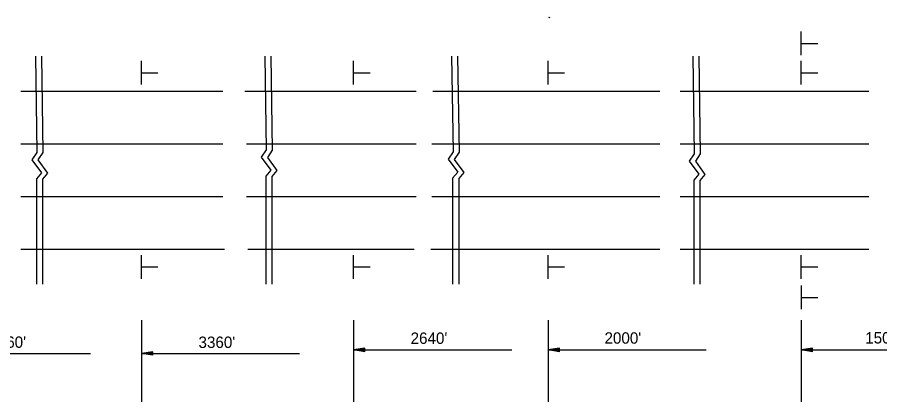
# Model space of a CAD drawing. Extents: x 1397271 to 1411271, y 376395 to 377888.
# Drawn here: x 1405137 to 1405825, y 377165 to 377471 of the extents above; entities that cross this region are included whole.
import ezdxf

# ---------------------------------------------------------------- set-up
doc = ezdxf.new("R2010")
doc.units = 0
doc.layers.add('Default', color=7, linetype='Continuous')
doc.layers.add('R_MOT', color=7, linetype='Continuous')

msp = doc.modelspace()

# ---------------------------------------------------------------- linework, layer by layer
at = {"layer": 'Default'}
for p, q in [((1405139.45, 377412.4), (1405300.59, 377412.4)), ((1405318.22, 377412.4), (1405454.76, 377412.4)), ((1405468.06, 377412.4), (1405649.17, 377412.4)), ((1405665.32, 377412.4), (1405815.76, 377412.4)), ((1405139.45, 377370.37), (1405300.59, 377370.37)), ((1405319.33, 377370.37), (1405454.76, 377370.37)), ((1405467.25, 377370.37), (1405649.17, 377370.37)), ((1405665.32, 377370.37), (1405815.76, 377370.37)), ((1405139.45, 377328.34), (1405300.59, 377328.34)), ((1405319.33, 377328.34), (1405454.76, 377328.34)), ((1405467.25, 377328.34), (1405649.17, 377328.34)), ((1405665.32, 377328.34), (1405815.76, 377328.34)), ((1405139.45, 377286.3), (1405301.98, 377286.3)), ((1405320.44, 377286.3), (1405453.12, 377286.3)), ((1405466.43, 377286.3), (1405649.17, 377286.3)), ((1405665.32, 377286.3), (1405815.76, 377286.3)), ((1405235.63, 377229.73), (1405235.63, 377164.82)), ((1405404.8, 377229.73), (1405404.8, 377164.82)), ((1405559.93, 377229.73), (1405559.93, 377164.82)), ((1405761.88, 377229.73), (1405761.88, 377164.82)), ((1405068.79, 377203.16), (1405194.97, 377203.16)), ((1405244.7, 377204.52), (1405235.63, 377203.16)), ((1405235.63, 377203.16), (1405361.81, 377203.16)), ((1405244.7, 377201.8), (1405235.63, 377203.16)), ((1405244.7, 377204.29), (1405237.15, 377203.16)), ((1405244.7, 377202.02), (1405237.15, 377203.16)), ((1405244.7, 377204.06), (1405238.7, 377203.16)), ((1405244.7, 377202.25), (1405238.7, 377203.16)), ((1405244.7, 377203.83), (1405240.21, 377203.16)), ((1405244.7, 377202.48), (1405240.21, 377203.16)), ((1405244.7, 377203.6), (1405241.75, 377203.16)), ((1405244.7, 377202.72), (1405241.75, 377203.16)), ((1405244.7, 377203.37), (1405243.27, 377203.16)), ((1405244.7, 377202.94), (1405243.27, 377203.16)), ((1405244.7, 377201.8), (1405244.7, 377204.52)), ((1405413.86, 377207.42), (1405404.8, 377206.06)), ((1405404.8, 377206.06), (1405530.98, 377206.06)), ((1405413.86, 377204.7), (1405404.8, 377206.06)), ((1405413.86, 377207.19), (1405406.31, 377206.06)), ((1405413.86, 377204.92), (1405406.31, 377206.06)), ((1405413.86, 377206.96), (1405407.87, 377206.06)), ((1405413.86, 377205.15), (1405407.87, 377206.06)), ((1405413.86, 377206.73), (1405409.38, 377206.06)), ((1405413.86, 377205.38), (1405409.38, 377206.06)), ((1405413.86, 377206.5), (1405410.92, 377206.06)), ((1405413.86, 377205.62), (1405410.92, 377206.06)), ((1405413.86, 377206.27), (1405412.43, 377206.06)), ((1405413.86, 377205.84), (1405412.43, 377206.06)), ((1405413.86, 377204.7), (1405413.86, 377207.42)), ((1405568.99, 377207.42), (1405559.93, 377206.06)), ((1405559.93, 377206.06), (1405686.11, 377206.06)), ((1405568.99, 377204.7), (1405559.93, 377206.06)), ((1405568.99, 377207.19), (1405561.44, 377206.06)), ((1405568.99, 377204.92), (1405561.44, 377206.06)), ((1405568.99, 377206.96), (1405563, 377206.06)), ((1405568.99, 377205.15), (1405563, 377206.06)), ((1405568.99, 377206.73), (1405564.51, 377206.06)), ((1405568.99, 377205.38), (1405564.51, 377206.06)), ((1405568.99, 377206.5), (1405566.05, 377206.06)), ((1405568.99, 377205.62), (1405566.05, 377206.06)), ((1405568.99, 377206.27), (1405567.56, 377206.06)), ((1405568.99, 377205.84), (1405567.56, 377206.06)), ((1405568.99, 377204.7), (1405568.99, 377207.42)), ((1405770.95, 377207.42), (1405761.88, 377206.06)), ((1405761.88, 377206.06), (1405888.06, 377206.06)), ((1405770.95, 377204.7), (1405761.88, 377206.06)), ((1405770.95, 377207.19), (1405763.39, 377206.06)), ((1405770.95, 377204.92), (1405763.39, 377206.06)), ((1405770.95, 377206.96), (1405764.95, 377206.06)), ((1405770.95, 377205.15), (1405764.95, 377206.06)), ((1405770.95, 377206.73), (1405766.46, 377206.06)), ((1405770.95, 377205.38), (1405766.46, 377206.06)), ((1405770.95, 377206.5), (1405768, 377206.06)), ((1405770.95, 377205.62), (1405768, 377206.06)), ((1405770.95, 377206.27), (1405769.51, 377206.06)), ((1405770.95, 377205.84), (1405769.51, 377206.06)), ((1405770.95, 377204.7), (1405770.95, 377207.42))]:
    msp.add_line(p, q, dxfattribs=at)
for points in [[(1405151.06, 377440.23), (1405152.22, 377363.49), (1405148.3, 377357.66), (1405155.95, 377347.19), (1405151.92, 377342.35), (1405151.9, 377258.48)], [(1405155.89, 377440.23), (1405157.05, 377363.29), (1405153.13, 377357.45), (1405160.78, 377346.99), (1405156.75, 377342.15), (1405156.74, 377258.47)], [(1405334.07, 377440.23), (1405335.21, 377365.59), (1405331.28, 377359.75), (1405338.93, 377349.28), (1405334.91, 377344.45), (1405334.89, 377258.48)], [(1405338.9, 377440.23), (1405340.04, 377365.39), (1405336.11, 377359.55), (1405343.76, 377349.08), (1405339.73, 377344.25), (1405339.72, 377258.48)], [(1405483.01, 377440.23), (1405484.17, 377364), (1405480.24, 377358.16), (1405487.89, 377347.7), (1405483.86, 377342.86), (1405483.85, 377258.48)], [(1405487.84, 377440.23), (1405489, 377363.8), (1405485.07, 377357.96), (1405492.72, 377347.49), (1405488.69, 377342.66), (1405488.68, 377258.48)], [(1405675.36, 377440.23), (1405676.54, 377362.48), (1405672.62, 377356.64), (1405680.27, 377346.17), (1405676.24, 377341.34), (1405676.22, 377258.48)], [(1405680.19, 377440.23), (1405681.37, 377362.27), (1405677.45, 377356.44), (1405685.1, 377345.97), (1405681.07, 377341.14), (1405681.06, 377258.48)]]:
    msp.add_lwpolyline(points, dxfattribs=at)
msp.add_arc((1405561.02, 377471.93), 1.05, 225.00009, 315, dxfattribs=at)
at = {"layer": 'R_MOT'}
for p, q in [((1405761.88, 377440.94), (1405761.88, 377459.85)), ((1405762.16, 377450.34), (1405775.07, 377450.34)), ((1405235.63, 377417.59), (1405235.63, 377436.5)), ((1405404.8, 377417.59), (1405404.8, 377436.5)), ((1405559.93, 377417.59), (1405559.93, 377436.5)), ((1405761.83, 377417.59), (1405761.83, 377436.5)), ((1405235.91, 377427), (1405248.82, 377427)), ((1405405.07, 377427), (1405417.99, 377427)), ((1405560.21, 377427), (1405573.12, 377427)), ((1405762.11, 377427), (1405775.02, 377427)), ((1405235.63, 377262.83), (1405235.63, 377281.74)), ((1405404.8, 377262.83), (1405404.8, 377281.74)), ((1405559.93, 377262.83), (1405559.93, 377281.74)), ((1405761.83, 377262.83), (1405761.83, 377281.74)), ((1405235.91, 377272.24), (1405248.82, 377272.24)), ((1405405.07, 377272.24), (1405417.99, 377272.24)), ((1405560.21, 377272.24), (1405573.12, 377272.24)), ((1405762.11, 377272.24), (1405775.02, 377272.24)), ((1405762.04, 377238.52), (1405762.04, 377257.44)), ((1405762.32, 377247.93), (1405775.23, 377247.93))]:
    msp.add_line(p, q, dxfattribs=at)

# ---------------------------------------------------------------- texts
at = {"layer": 'Default'}
for s, p in [("3960'", (1405114.32, 377207.78)), ("3360'", (1405281.16, 377207.67)), ("2640'", (1405450.33, 377210.93)), ("2000'", (1405604.96, 377211.07)), ("1500'", (1405812.91, 377211.22))]:
    msp.add_text(s, height=9.067, dxfattribs=at).set_placement(p)

doc.saveas('drawing.dxf')
